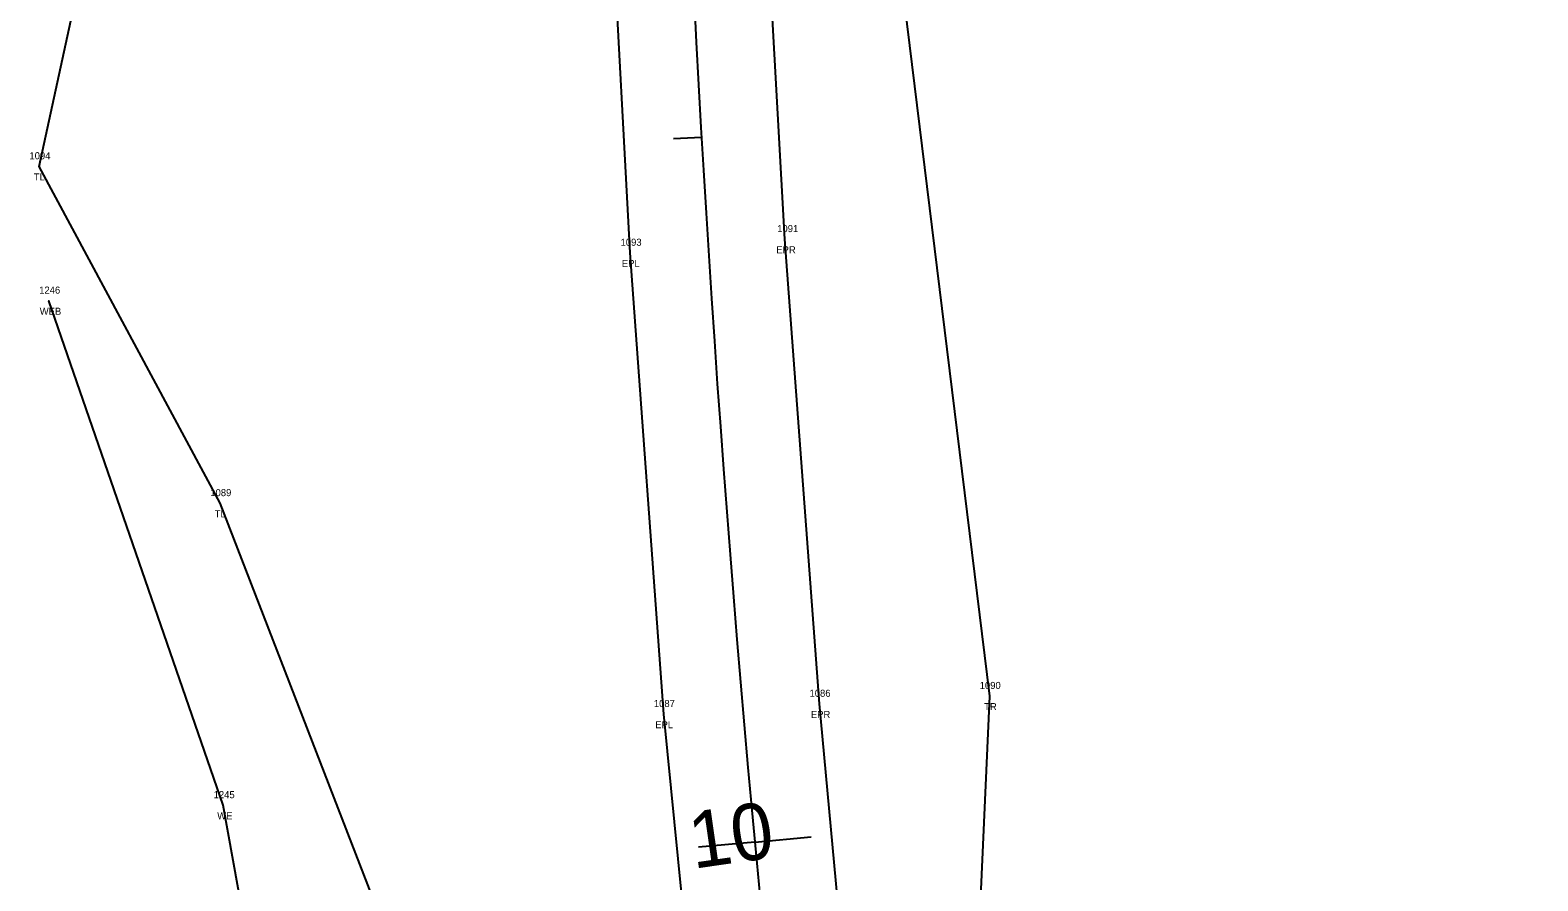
# Model space of a CAD drawing. Extents: x 2445178 to 2446205, y 790762 to 792372.
# Drawn here: x 2445598.5 to 2445811.8, y 791898.3 to 792018.7 of the extents above; entities that cross this region are included whole.
import ezdxf

# ---------------------------------------------------------------- set-up
doc = ezdxf.new("R2010")
doc.units = 0
for name, color, linetype in [('RD_EX_H2O', 7, 'Continuous'), ('RD_EX_H2O_txCode', 7, 'Continuous'), ('RD_EX_Road', 7, 'Continuous'), ('RD_EX_Road_txCode', 7, 'Continuous'), ('RD_EX_VEG', 7, 'Continuous'), ('RD_EX_VEG_txCode', 7, 'Continuous'), ('RD_HC_Cl', 7, 'Continuous'), ('RD_HC_Data_Tic', 7, 'Continuous'), ('RD_HC_TX_Sta50', 7, 'Continuous'), ('RD_SMD_Locator', 7, 'Continuous')]:
    doc.layers.add(name, color=color, linetype=linetype)

msp = doc.modelspace()

# ---------------------------------------------------------------- linework, layer by layer
at = {"layer": 'RD_EX_H2O'}
msp.add_lwpolyline([(2445757.3, 791817.48), (2445724.23, 791814.58), (2445698.23, 791807.38), (2445689.87, 791803.29), (2445658, 791800.52), (2445641.81, 791830.07), (2445642.32, 791839.59), (2445634.31, 791862.06), (2445625.81, 791909.02), (2445601.16, 791980.42)], dxfattribs=at)
at = {"layer": 'RD_EX_Road'}
for points in [[(2445780.98, 791497.5), (2445766.72, 791558.1), (2445751.9, 791628.3), (2445743.63, 791673.52), (2445732.07, 791741.61), (2445728.16, 791765.65), (2445723.56, 791768), (2445722.11, 791770.23), (2445723.91, 791773.52), (2445727.13, 791775.28), (2445723.51, 791799.48), (2445721.07, 791816.02), (2445719.51, 791817.06), (2445719.65, 791821.33), (2445720.29, 791823.76), (2445714.87, 791872.94), (2445710.18, 791923.37), (2445705.3, 791989.12), (2445702.81, 792033.07), (2445700.66, 792091.77), (2445697.78, 792201.78), (2445695.41, 792302.8)], [(2445850.42, 791174.36), (2445823.13, 791264.7), (2445806.34, 791321.46), (2445789.41, 791379.89), (2445773.46, 791437.57), (2445759.36, 791494.22), (2445744.01, 791559.83), (2445740.09, 791577.64), (2445731.05, 791621.01), (2445722.21, 791669.43), (2445711, 791738.26), (2445706.49, 791765.2), (2445707.32, 791765.82), (2445706.36, 791771.19), (2445705.53, 791771.38), (2445701.96, 791795.92), (2445699.57, 791813.34), (2445693.24, 791870.48), (2445688.14, 791921.92), (2445683.42, 791987.19), (2445680.88, 792033.67), (2445678.74, 792090.55), (2445675.91, 792199.23), (2445673.61, 792301.11)]]:
    msp.add_lwpolyline(points, dxfattribs=at)
at = {"layer": 'RD_EX_VEG'}
for points in [[(2445687.12, 791815.07), (2445675.71, 791865.82), (2445647.64, 791894.24), (2445625.38, 791951.76), (2445599.8, 791999.43), (2445616.22, 792074.95), (2445645.15, 792198.05), (2445661.49, 792301.38)], [(2445729.92, 791827.7), (2445734.27, 791924.48), (2445719.05, 792048.41), (2445719.1, 792091.3), (2445713.04, 792300.82)]]:
    msp.add_lwpolyline(points, dxfattribs=at)
at = {"layer": 'RD_HC_Cl'}
msp.add_arc((2448553.48, 792169.37), 2864.79, 181.3527, 196.84356, dxfattribs=at)
at = {"layer": 'RD_HC_Data_Tic'}
for p, q in [((2445693.5, 792003.53), (2445689.51, 792003.3)), ((2445701.03, 791903.82), (2445693.06, 791903.07)), ((2445701.03, 791903.82), (2445708.99, 791904.56))]:
    msp.add_line(p, q, dxfattribs=at)
at = {"layer": 'RD_SMD_Locator'}
for centre in [(2445599.8, 791999.43), (2445705.3, 791989.12), (2445683.42, 791987.19), (2445601.16, 791980.42), (2445625.38, 791951.76), (2445734.27, 791924.48), (2445710.18, 791923.37), (2445688.14, 791921.92), (2445625.81, 791909.02)]:
    msp.add_circle(centre, 0.001, dxfattribs=at)

# ---------------------------------------------------------------- texts
at = {"layer": 'RD_EX_H2O_txCode'}
for s, p in [('1246', (2445599.79, 791981.42)), ('WEB', (2445599.87, 791978.42)), ('1245', (2445624.47, 791910.02)), ('WE', (2445624.98, 791907.02))]:
    msp.add_text(s, height=1, dxfattribs=at).set_placement(p)
at = {"layer": 'RD_EX_Road_txCode'}
for s, p in [('1091', (2445704.2, 791990.12)), ('1093', (2445682.04, 791988.19)), ('EPR', (2445704.07, 791987.12)), ('EPL', (2445682.22, 791985.19)), ('1086', (2445708.77, 791924.37)), ('1087', (2445686.75, 791922.92)), ('EPR', (2445708.96, 791921.37)), ('EPL', (2445686.94, 791919.92))]:
    msp.add_text(s, height=1, dxfattribs=at).set_placement(p)
at = {"layer": 'RD_EX_VEG_txCode'}
for s, p in [('1094', (2445598.41, 792000.43)), ('TL', (2445599.02, 791997.43)), ('1089', (2445624, 791952.76)), ('TL', (2445624.61, 791949.76)), ('1090', (2445732.85, 791925.48)), ('TR', (2445733.48, 791922.48))]:
    msp.add_text(s, height=1, dxfattribs=at).set_placement(p)
at = {"layer": 'RD_HC_TX_Sta50'}
msp.add_text('10', height=8, rotation=8.1698, dxfattribs=at).set_placement((2445692.32, 791900.02))

doc.saveas('drawing.dxf')
